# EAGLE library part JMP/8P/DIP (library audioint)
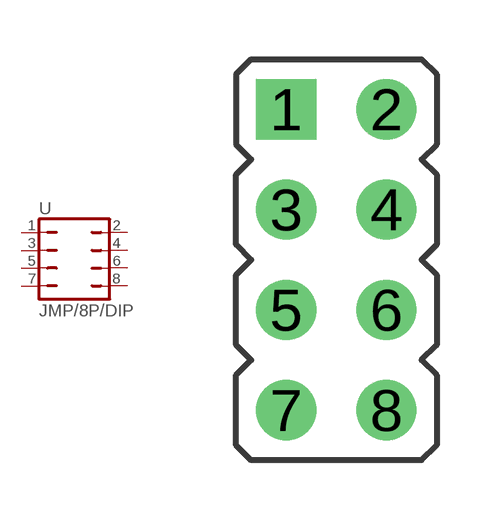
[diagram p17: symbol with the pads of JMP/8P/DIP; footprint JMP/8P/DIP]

Designator prefix -

## JMP/8P/DIP  [JMP/8P/DIP]
1  1  pas
2  2  pas
3  3  pas
4  4  pas
5  5  pas
6  6  pas
7  7  pas
8  8  pas

## Footprint JMP/8P/DIP (pad centres in mm)
drill 0.914 pad 1.524 square: 1 -1.27,3.81
drill 0.914 pad 1.524 round: 2 1.27,3.81; 3 -1.27,1.27; 4 1.27,1.27; 5 -1.27,-1.27; 6 1.27,-1.27; 7 -1.27,-3.81; 8 1.27,-3.81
